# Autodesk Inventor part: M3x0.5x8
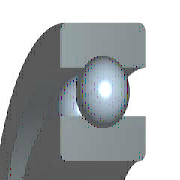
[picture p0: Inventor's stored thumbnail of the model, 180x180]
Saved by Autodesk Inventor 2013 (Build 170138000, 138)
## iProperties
Created: 2009-02
Part Number: M3x0.5x8
Material: 강, 연강
Description: 깊은 그루브 볼 베어링
Document SubType Name: Modeling
Standard: KS B 2023
Designer: KYOUNG IL JANG
Standards Organization: KS
Language: ko-KR
Size Designation: 6202 - 15 x 35 x 11
Categories: <MemberInstance><Categories><Category DisplayName="샤프트 부품" InternalName="7f7aeb1f-a693-4053-b835-cee3144e0d98" Mnemonic="SHFT"><Category DisplayName="베어링" Inter
Density: 7.86 g/cm^3
Mass: 45.8725 g
Surface Area: 51.5584 cm^2
Volume: 5.83619 cm^3
Vendor: CBT Solutions
Company: 한국ATC센터
IsCustomPart: 1
Author: KYOUNG IL JANG
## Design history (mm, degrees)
sketch "스케치" dims "d0" = 5.2 (= -0.26 x WD + 0.26 x BD)
  geometry: L1 (2.9, 12.5)-(8.1, 12.5); L2 (5.5, 12.5)-(5.5, 9.9); L3 (5.5, 12.5)-(5.5, 15.1); L4 (3.568, 10.76)-(0, 10.76); L5 (0, 7.5)-(11, 7.5); L6 (3.568, 14.24)-(0, 14.24); L7 (0, 17.5)-(11, 17.5); L8 (11, 7.5)-(11, 10.76); L9 (7.432, 10.76)-(11, 10.76); L10 (7.432, 14.24)-(11, 14.24); L11 (11, 17.5)-(11, 14.24); L12 (-1.4, 0)-(8.4, 0) reference; L13 (0, -0.3)-(0, 5.3) reference
  constraints: 22 end point, 4 point on line, 2 collinear, 2 perpendicular, 2 symmetric about line, 1 midpoint, 1 parallel, 14 other
  dimensions: "d9" = 15 diameter of L5 L12 (= WD); "d11" = 35 diameter of L7 L12 (= BD); "d12" = 11 distance between parallel lines of L8 L13 (= KB); "d13" = 21.52 diameter of L9 L12 (= 0.326 x BD + 0.674 x WD)
revolve "본체" stored, may be unused: angle "d6" = 90 deg
revolve "볼" stored, may be unused: angle "d7" = 90 deg
pattern_circular "IDS_ARRAYBALL[SIMPL:T]" dims angle "d3" = 360 deg
body "Solid1"
fillet "모깎기1" dims "d1" = 0.6 (= KRS)
other parameters: "WD" = 15 [user parameter; used in 5 equation terms], "BD" = 35 [user parameter; used in 5 equation terms], "KB" = 11 [user parameter; used in 1 equation term], "KRS" = 0.6 [user parameter; used in 1 equation term], "d4" = 0, "d5" = 0, "d8" = 0, "d14" = 0, "d15" = 0, "BBA" = 0 [user parameter], "BC0" = 3750000 [user parameter], "BC" = 7800000 [user parameter], "BR" = 17.5 (= 0.5 x BD) [user parameter], "WR" = 7.5 (= 0.5 x WD) [user parameter]
